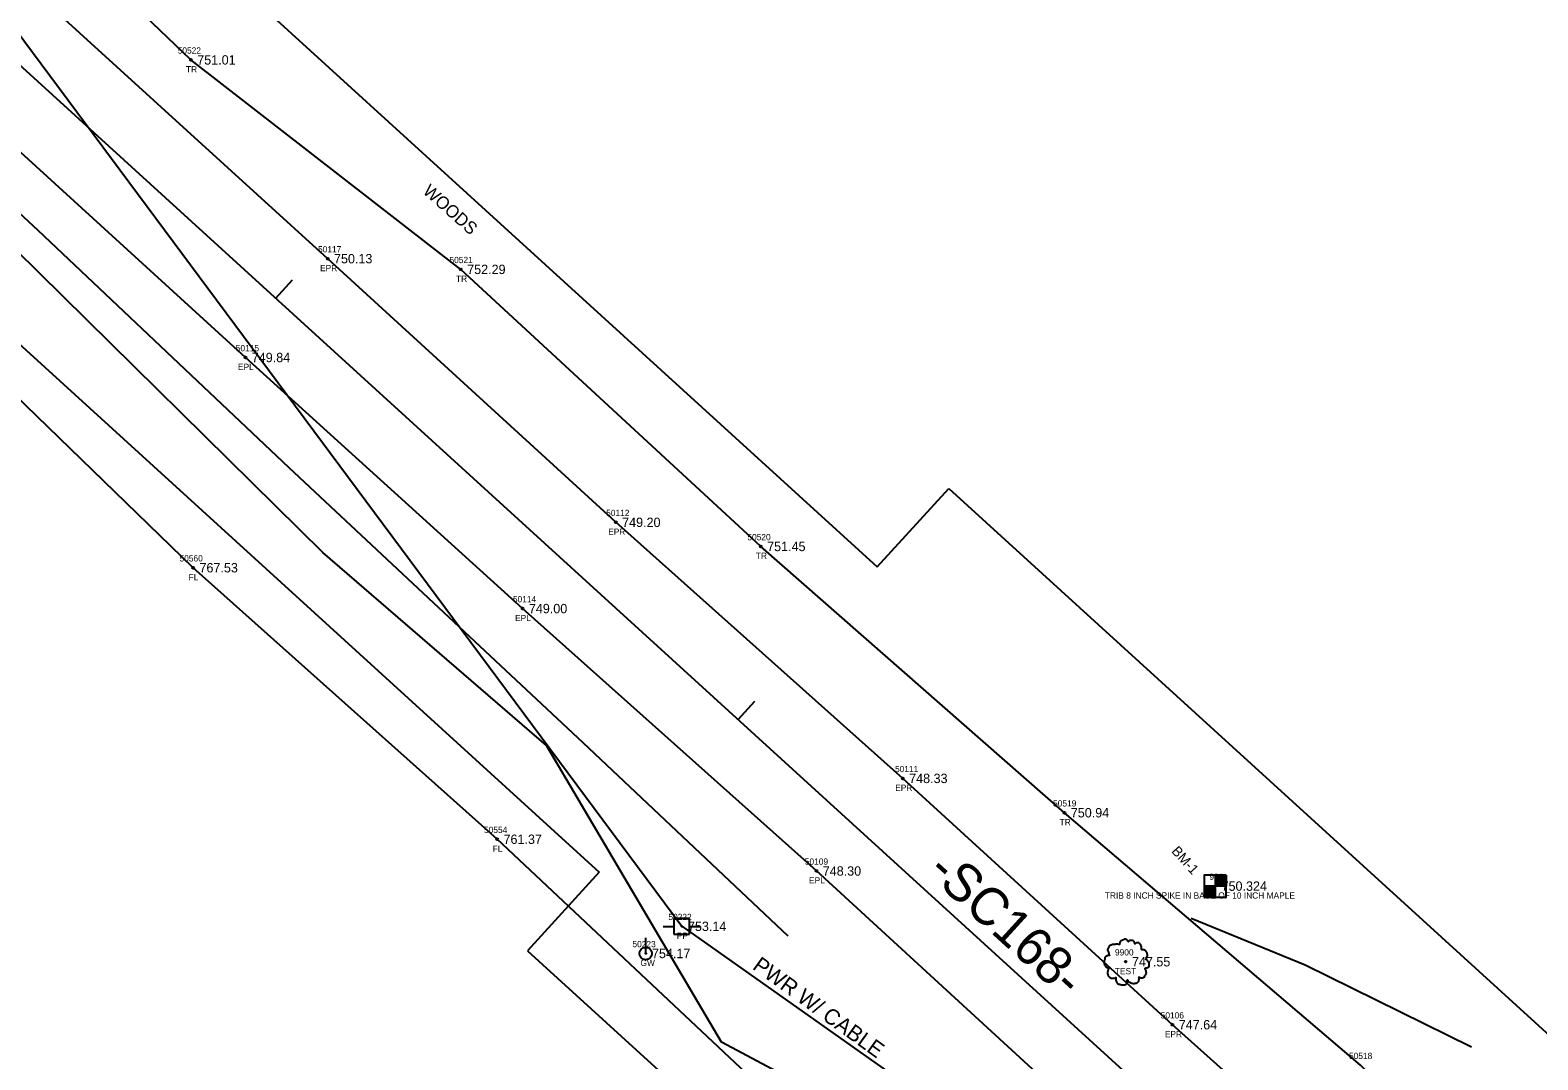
# Model space of a CAD drawing. Extents: x 1378245 to 1381654, y 996521 to 1000567.
# Drawn here: x 1379299.2 to 1379540.2, y 999152.7 to 999317.3 of the extents above; entities that cross this region are included whole.
import ezdxf

# ---------------------------------------------------------------- set-up
doc = ezdxf.new("R2010")
doc.units = 0
for name, color, linetype in [('RD_EX_Fence_Other', 7, 'Continuous'), ('RD_EX_Fence_Other_txCode', 7, 'Continuous'), ('RD_EX_H2O', 7, 'Continuous'), ('RD_EX_Road', 7, 'Continuous'), ('RD_EX_Road_txCode', 7, 'Continuous'), ('RD_EX_RW', 7, 'Continuous'), ('RD_EX_SU_Elec', 7, 'Continuous'), ('RD_EX_TX_Fence_Other_ELEV', 7, 'Continuous'), ('RD_EX_TX_Road_ELEV', 7, 'Continuous'), ('RD_EX_TX_UT_ELEV', 7, 'Continuous'), ('RD_EX_TX_VEG_ELEV', 7, 'Continuous'), ('RD_EX_UT', 7, 'Continuous'), ('RD_EX_UT_txCode', 7, 'Continuous'), ('RD_EX_VEG', 7, 'Continuous'), ('RD_EX_VEG_txCode', 7, 'Continuous'), ('RD_HC_Cl', 7, 'Continuous'), ('RD_HC_Data', 7, 'Continuous'), ('RD_HC_Data_Tic', 7, 'Continuous'), ('RD_HC_Survey', 7, 'Continuous'), ('RD_HC_Survey_ELEV', 7, 'Continuous'), ('RD_HC_Survey_txCode', 7, 'Continuous'), ('RD_SMD_Locator', 7, 'Continuous'), ('RD_TX_Misc1', 7, 'Continuous'), ('RD_TX_Misc2', 7, 'Continuous'), ('RD_TX_Utilities', 7, 'Continuous')]:
    doc.layers.add(name, color=color, linetype=linetype)

msp = doc.modelspace()

# ---------------------------------------------------------------- linework, layer by layer
at = {"layer": 'RD_EX_Fence_Other'}
msp.add_lwpolyline([(1379613.24, 998940.87), (1379574.4, 998986.01), (1379543.59, 999020.83), (1379505.83, 999062.54), (1379472.56, 999095.44), (1379454.3, 999112.36), (1379373.85, 999187.96), (1379325.25, 999231.37), (1379289.51, 999266.01), (1379255.48, 999295.15), (1379213.9, 999334), (1379169.28, 999374.93), (1379148.65, 999391.69), (1379140.06, 999386.4)], dxfattribs=at)
at = {"layer": 'RD_EX_H2O'}
for points in [[(1379420.33, 999172.47), (1379387.59, 999203.38), (1379340.59, 999247.33), (1379300.46, 999285.26), (1379267.64, 999315.76), (1379232.14, 999347.36), (1379190.43, 999387.13)], [(1379484.77, 999175.36), (1379503.01, 999167.88), (1379529.58, 999154.75)]]:
    msp.add_lwpolyline(points, dxfattribs=at)
at = {"layer": 'RD_EX_Road'}
for points in [[(1379637.07, 998987.22), (1379597.14, 999025.68), (1379553.31, 999065.91), (1379510.7, 999104.3), (1379468.49, 999142.89), (1379424.88, 999182.89), (1379377.9, 999224.84), (1379333.61, 999264.98), (1379287.28, 999307.21), (1379240.78, 999348.98)], [(1379652.22, 999003.54), (1379610.67, 999040.91), (1379567.41, 999079.79), (1379524.77, 999119.81), (1379481.79, 999158.31), (1379438.69, 999197.69), (1379392.81, 999238.63), (1379346.75, 999280.78), (1379301.8, 999321.66)]]:
    msp.add_lwpolyline(points, dxfattribs=at)
at = {"layer": 'RD_EX_RW'}
for p, q in [((1378622.31, 999971.52), (1379434.58, 999231.49)), ((1378575.71, 999924.69), (1379390.13, 999182.7)), ((1379434.58, 999231.49), (1379446.02, 999244.05)), ((1379446.02, 999244.05), (1379815.63, 998907.31)), ((1379390.13, 999182.7), (1379378.68, 999170.13)), ((1379378.68, 999170.13), (1379748.28, 998833.39))]:
    msp.add_line(p, q, dxfattribs=at)
at = {"layer": 'RD_EX_SU_Elec'}
msp.add_lwpolyline([(1378514.25, 999944.12), (1378777.7, 999831.22), (1379190.17, 999461.05), (1379403.33, 999174.04), (1379756.94, 998924.25), (1380051.16, 998659.97), (1380327.91, 998390.65), (1380546.23, 998058.37)], dxfattribs=at)
at = {"layer": 'RD_EX_UT'}
for p, q in [((1379400.36, 999174.02), (1379402.09, 999174.02)), ((1379404.57, 999175.3), (1379402.07, 999175.3)), ((1379402.07, 999175.3), (1379402.07, 999172.8)), ((1379404.54, 999174.02), (1379406.36, 999174.02)), ((1379404.57, 999172.8), (1379404.57, 999175.3)), ((1379397.58, 999169.7), (1379397.58, 999172.2)), ((1379402.07, 999172.8), (1379404.57, 999172.8))]:
    msp.add_line(p, q, dxfattribs=at)
msp.add_circle((1379397.58, 999169.7), 1, dxfattribs=at)
at = {"layer": 'RD_EX_VEG'}
for points in [[(1379635.72, 999031.86), (1379598.35, 999066.81), (1379553.67, 999109.8), (1379511.83, 999151.82), (1379464.53, 999192.2), (1379415.99, 999234.77), (1379368.04, 999279.07), (1379324.89, 999312.56), (1379291.58, 999344.45), (1379199.89, 999450.8), (1379227.01, 999457.75)], [(1379621.71, 998986.05), (1379558.91, 999039.89), (1379518.45, 999079.04), (1379470.36, 999123.18), (1379409.67, 999155.52), (1379381.73, 999202.94), (1379345.95, 999233.83), (1379296.88, 999282.18), (1379264.05, 999313.51), (1379229.78, 999344.81), (1379187.41, 999381.54), (1379155.41, 999406.5), (1379144.25, 999379.18), (1379133.7, 999360.09), (1379119.62, 999335.97)]]:
    msp.add_lwpolyline(points, dxfattribs=at)
for centre, radius in [((1379474.3, 999168.38), 0.125), ((1379474.29, 999168.37), 0.00005)]:
    msp.add_circle(centre, radius, dxfattribs=at)
for points in [[(1379474.37, 999171.96), (1379474.22, 999171.98), (1379474.05, 999171.93), (1379473.93, 999171.88), (1379473.82, 999171.84), (1379473.7, 999171.79), (1379473.55, 999171.7), (1379473.44, 999171.6), (1379473.38, 999171.48), (1379473.35, 999171.36), (1379473.33, 999171.23), (1379473.33, 999171.14), (1379473.27, 999171.13), (1379473.19, 999171.14), (1379473.07, 999171.18), (1379472.94, 999171.18), (1379472.82, 999171.18), (1379472.64, 999171.16), (1379472.47, 999171.16), (1379472.33, 999171.14), (1379472.17, 999171.11), (1379471.98, 999171.05), (1379471.81, 999170.99), (1379471.66, 999170.86), (1379471.53, 999170.63), (1379471.47, 999170.45), (1379471.39, 999170.33), (1379471.47, 999170.1), (1379471.56, 999169.93), (1379471.57, 999169.83), (1379471.61, 999169.61), (1379471.66, 999169.5), (1379471.72, 999169.4), (1379471.68, 999169.39), (1379471.49, 999169.36), (1379471.34, 999169.31), (1379471.13, 999169.2), (1379471.02, 999169.09), (1379470.97, 999168.93), (1379470.96, 999168.75), (1379470.91, 999168.65), (1379470.87, 999168.52), (1379470.86, 999168.48), (1379470.83, 999168.32), (1379470.88, 999168.09), (1379470.89, 999167.92), (1379470.96, 999167.8), (1379471.03, 999167.72), (1379471.12, 999167.59), (1379471.32, 999167.48), (1379471.48, 999167.43), (1379471.58, 999167.42), (1379471.49, 999167.17), (1379471.47, 999166.99), (1379471.41, 999166.79), (1379471.41, 999166.75), (1379471.38, 999166.52), (1379471.46, 999166.35), (1379471.49, 999166.17), (1379471.58, 999166.05), (1379471.72, 999165.9), (1379471.88, 999165.79), (1379472.13, 999165.73), (1379472.33, 999165.74), (1379472.62, 999165.83), (1379472.74, 999165.87), (1379472.73, 999165.78), (1379472.74, 999165.59), (1379472.74, 999165.38), (1379472.82, 999165.22), (1379472.87, 999165.08), (1379472.94, 999164.95), (1379473.11, 999164.84), (1379473.3, 999164.8), (1379473.52, 999164.73), (1379473.74, 999164.69), (1379473.99, 999164.68), (1379474.29, 999164.75), (1379474.43, 999164.82), (1379474.48, 999164.9), (1379474.58, 999165.09), (1379474.55, 999165.2), (1379474.57, 999165.5), (1379474.62, 999165.42), (1379474.7, 999165.24), (1379474.95, 999165.09), (1379475.15, 999165), (1379475.39, 999164.93), (1379475.54, 999164.89), (1379475.78, 999164.93), (1379475.97, 999164.97), (1379476.15, 999165.03), (1379476.3, 999165.17), (1379476.39, 999165.3), (1379476.42, 999165.44), (1379476.45, 999165.63), (1379476.48, 999165.72)], [(1379476.48, 999165.72), (1379476.44, 999165.8), (1379476.42, 999165.93), (1379476.45, 999165.92), (1379476.54, 999165.89), (1379476.68, 999165.83), (1379476.79, 999165.79), (1379476.95, 999165.8), (1379477.09, 999165.85), (1379477.32, 999165.99), (1379477.45, 999166.23), (1379477.59, 999166.43), (1379477.63, 999166.59), (1379477.6, 999166.7), (1379477.59, 999166.95), (1379477.49, 999167.08), (1379477.47, 999167.14), (1379477.42, 999167.34), (1379477.45, 999167.37), (1379477.59, 999167.39), (1379477.78, 999167.45), (1379477.92, 999167.52), (1379478.03, 999167.6), (1379478.07, 999167.72), (1379478.05, 999167.92), (1379478.08, 999168.12), (1379478.04, 999168.19), (1379477.99, 999168.27), (1379477.95, 999168.37), (1379477.88, 999168.44), (1379477.83, 999168.52), (1379477.78, 999168.57), (1379477.72, 999168.64), (1379477.63, 999168.7), (1379477.55, 999168.73), (1379477.53, 999168.8), (1379477.6, 999168.9), (1379477.63, 999168.95), (1379477.64, 999169.06), (1379477.75, 999169.24), (1379477.78, 999169.44), (1379477.75, 999169.65), (1379477.73, 999169.79), (1379477.65, 999169.93), (1379477.55, 999170.05), (1379477.49, 999170.14), (1379477.4, 999170.2), (1379477.24, 999170.26), (1379477.12, 999170.29), (1379476.94, 999170.29), (1379476.84, 999170.31), (1379476.85, 999170.34), (1379476.85, 999170.41), (1379476.85, 999170.55), (1379476.82, 999170.78), (1379476.74, 999171.03), (1379476.74, 999171.04), (1379476.69, 999171.16), (1379476.58, 999171.26), (1379476.49, 999171.31), (1379476.39, 999171.38), (1379476.27, 999171.39), (1379476.12, 999171.39), (1379475.98, 999171.36), (1379475.88, 999171.31), (1379475.79, 999171.25), (1379475.75, 999171.33), (1379475.7, 999171.48), (1379475.68, 999171.55), (1379475.6, 999171.64), (1379475.49, 999171.74), (1379475.27, 999171.8), (1379474.95, 999171.76), (1379474.8, 999171.66), (1379474.73, 999171.58), (1379474.7, 999171.64), (1379474.6, 999171.74), (1379474.55, 999171.83), (1379474.47, 999171.89), (1379474.39, 999171.94), (1379474.34, 999171.96)]]:
    msp.add_spline(points, degree=3, dxfattribs=at)
at = {"layer": 'RD_HC_Cl'}
msp.add_line((1378781.54, 999781.8), (1380217.09, 998473.92), dxfattribs=at)
at = {"layer": 'RD_HC_Data_Tic'}
for p, q in [((1379338.43, 999274.44), (1379341.12, 999277.4)), ((1379412.35, 999207.09), (1379415.04, 999210.05))]:
    msp.add_line(p, q, dxfattribs=at)
at = {"layer": 'RD_HC_Survey'}
for p, q in [((1379488.63, 999182.24), (1379488.63, 999178.7)), ((1379488.64, 999182.24), (1379488.64, 999180.47)), ((1379488.67, 999182.24), (1379488.67, 999180.47)), ((1379488.69, 999182.24), (1379488.69, 999180.47)), ((1379488.72, 999182.24), (1379488.72, 999180.47)), ((1379488.74, 999182.24), (1379488.74, 999180.47)), ((1379488.77, 999182.24), (1379488.77, 999180.47)), ((1379488.79, 999182.24), (1379488.79, 999180.47)), ((1379488.82, 999182.24), (1379488.82, 999180.47)), ((1379488.84, 999182.24), (1379488.84, 999180.47)), ((1379488.87, 999182.24), (1379488.87, 999180.47)), ((1379488.89, 999182.24), (1379488.89, 999180.47)), ((1379488.92, 999182.24), (1379488.92, 999180.47)), ((1379488.94, 999182.24), (1379488.94, 999180.47)), ((1379488.97, 999182.24), (1379488.97, 999180.47)), ((1379488.99, 999182.24), (1379488.99, 999180.47)), ((1379489.02, 999182.24), (1379489.02, 999180.47)), ((1379489.04, 999182.24), (1379489.04, 999180.47)), ((1379489.07, 999182.24), (1379489.07, 999180.47)), ((1379489.09, 999182.24), (1379489.09, 999180.47)), ((1379489.12, 999182.24), (1379489.12, 999180.47)), ((1379489.14, 999182.24), (1379489.14, 999180.47)), ((1379489.17, 999182.24), (1379489.17, 999180.47)), ((1379489.19, 999182.24), (1379489.19, 999180.47)), ((1379489.22, 999182.24), (1379489.22, 999180.47)), ((1379489.24, 999182.24), (1379489.24, 999180.47)), ((1379489.27, 999182.24), (1379489.27, 999180.47)), ((1379489.29, 999182.24), (1379489.29, 999180.47)), ((1379489.32, 999182.24), (1379489.32, 999180.47)), ((1379489.34, 999182.24), (1379489.34, 999180.47)), ((1379489.37, 999182.24), (1379489.37, 999180.47)), ((1379489.39, 999182.24), (1379489.39, 999180.47)), ((1379489.42, 999182.24), (1379489.42, 999180.47)), ((1379489.44, 999182.24), (1379489.44, 999180.47)), ((1379489.47, 999182.24), (1379489.47, 999180.47)), ((1379489.49, 999182.24), (1379489.49, 999180.47)), ((1379489.52, 999182.24), (1379489.52, 999180.47)), ((1379489.54, 999182.24), (1379489.54, 999180.47)), ((1379489.57, 999182.24), (1379489.57, 999180.47)), ((1379489.59, 999182.24), (1379489.59, 999180.47)), ((1379489.62, 999182.24), (1379489.62, 999180.47)), ((1379489.64, 999182.24), (1379489.64, 999180.47)), ((1379489.67, 999182.24), (1379489.67, 999180.47)), ((1379489.69, 999182.24), (1379489.69, 999180.47)), ((1379489.72, 999182.24), (1379489.72, 999180.47)), ((1379489.74, 999182.24), (1379489.74, 999180.47)), ((1379489.77, 999182.24), (1379489.77, 999180.47)), ((1379489.79, 999182.24), (1379489.79, 999180.47)), ((1379489.82, 999182.24), (1379489.82, 999180.47)), ((1379489.84, 999182.24), (1379489.84, 999180.47)), ((1379489.87, 999182.24), (1379489.87, 999180.47)), ((1379489.89, 999182.24), (1379489.89, 999180.47)), ((1379489.92, 999182.24), (1379489.92, 999180.47)), ((1379489.94, 999182.24), (1379489.94, 999180.47)), ((1379489.97, 999182.24), (1379489.97, 999180.47)), ((1379489.99, 999182.24), (1379489.99, 999180.47)), ((1379490.02, 999182.24), (1379490.02, 999180.47)), ((1379490.04, 999182.24), (1379490.04, 999180.47)), ((1379490.07, 999182.24), (1379490.07, 999180.47)), ((1379490.09, 999182.24), (1379490.09, 999180.47)), ((1379490.12, 999182.24), (1379490.12, 999180.47)), ((1379490.14, 999182.24), (1379490.14, 999180.47)), ((1379490.17, 999182.24), (1379490.17, 999180.47)), ((1379490.19, 999182.24), (1379490.19, 999180.47)), ((1379490.22, 999182.24), (1379490.22, 999180.47)), ((1379490.24, 999182.24), (1379490.24, 999180.47)), ((1379490.27, 999182.24), (1379490.27, 999180.47)), ((1379490.29, 999182.24), (1379490.29, 999180.47)), ((1379490.32, 999182.24), (1379490.32, 999180.47)), ((1379490.34, 999182.24), (1379490.34, 999180.47)), ((1379490.37, 999182.24), (1379490.37, 999180.47)), ((1379490.39, 999180.47), (1379486.86, 999180.47)), ((1379486.86, 999180.47), (1379486.86, 999178.7)), ((1379486.88, 999180.47), (1379486.88, 999178.7)), ((1379486.91, 999180.47), (1379486.91, 999178.7)), ((1379486.93, 999180.47), (1379486.93, 999178.7)), ((1379486.96, 999180.47), (1379486.96, 999178.7)), ((1379486.98, 999180.47), (1379486.98, 999178.7)), ((1379487.01, 999180.47), (1379487.01, 999178.7)), ((1379487.03, 999180.47), (1379487.03, 999178.7)), ((1379487.06, 999180.47), (1379487.06, 999178.7)), ((1379487.08, 999180.47), (1379487.08, 999178.7)), ((1379487.11, 999180.47), (1379487.11, 999178.7)), ((1379487.13, 999180.47), (1379487.13, 999178.7)), ((1379487.16, 999180.47), (1379487.16, 999178.7)), ((1379487.18, 999180.47), (1379487.18, 999178.7)), ((1379487.21, 999180.47), (1379487.21, 999178.7)), ((1379487.23, 999180.47), (1379487.23, 999178.7)), ((1379487.26, 999180.47), (1379487.26, 999178.7)), ((1379487.28, 999180.47), (1379487.28, 999178.7)), ((1379487.31, 999180.47), (1379487.31, 999178.7)), ((1379487.33, 999180.47), (1379487.33, 999178.7)), ((1379487.36, 999180.47), (1379487.36, 999178.7)), ((1379487.38, 999180.47), (1379487.38, 999178.7)), ((1379487.41, 999180.47), (1379487.41, 999178.7)), ((1379487.43, 999180.47), (1379487.43, 999178.7)), ((1379487.46, 999180.47), (1379487.46, 999178.7)), ((1379487.48, 999180.47), (1379487.48, 999178.7)), ((1379487.51, 999180.47), (1379487.51, 999178.7)), ((1379487.53, 999180.47), (1379487.53, 999178.7)), ((1379487.56, 999180.47), (1379487.56, 999178.7)), ((1379487.58, 999180.47), (1379487.58, 999178.7)), ((1379487.61, 999180.47), (1379487.61, 999178.7)), ((1379487.63, 999180.47), (1379487.63, 999178.7)), ((1379487.66, 999180.47), (1379487.66, 999178.7)), ((1379487.68, 999180.47), (1379487.68, 999178.7)), ((1379487.71, 999180.47), (1379487.71, 999178.7)), ((1379487.73, 999180.47), (1379487.73, 999178.7)), ((1379487.76, 999180.47), (1379487.76, 999178.7)), ((1379487.78, 999180.47), (1379487.78, 999178.7)), ((1379487.81, 999180.47), (1379487.81, 999178.7)), ((1379487.83, 999180.47), (1379487.83, 999178.7)), ((1379487.86, 999180.47), (1379487.86, 999178.7)), ((1379487.88, 999180.47), (1379487.88, 999178.7)), ((1379487.91, 999180.47), (1379487.91, 999178.7)), ((1379487.93, 999180.47), (1379487.93, 999178.7)), ((1379487.96, 999180.47), (1379487.96, 999178.7)), ((1379487.98, 999180.47), (1379487.98, 999178.7)), ((1379488.01, 999180.47), (1379488.01, 999178.7)), ((1379488.03, 999180.47), (1379488.03, 999178.7)), ((1379488.06, 999180.47), (1379488.06, 999178.7)), ((1379488.08, 999180.47), (1379488.08, 999178.7)), ((1379488.11, 999180.47), (1379488.11, 999178.7)), ((1379488.13, 999180.47), (1379488.13, 999178.7)), ((1379488.16, 999180.47), (1379488.16, 999178.7)), ((1379488.18, 999180.47), (1379488.18, 999178.7)), ((1379488.21, 999180.47), (1379488.21, 999178.7)), ((1379488.23, 999180.47), (1379488.23, 999178.7)), ((1379488.26, 999180.47), (1379488.26, 999178.7)), ((1379488.28, 999180.47), (1379488.28, 999178.7)), ((1379488.31, 999180.47), (1379488.31, 999178.7)), ((1379488.33, 999180.47), (1379488.33, 999178.7)), ((1379488.36, 999180.47), (1379488.36, 999178.7)), ((1379488.38, 999180.47), (1379488.38, 999178.7)), ((1379488.41, 999180.47), (1379488.41, 999178.7)), ((1379488.43, 999180.47), (1379488.43, 999178.7)), ((1379488.46, 999180.47), (1379488.46, 999178.7)), ((1379488.48, 999180.47), (1379488.48, 999178.7)), ((1379488.51, 999180.47), (1379488.51, 999178.7)), ((1379488.53, 999180.47), (1379488.53, 999178.7)), ((1379488.56, 999180.47), (1379488.56, 999178.7)), ((1379488.58, 999180.47), (1379488.58, 999178.7)), ((1379488.61, 999180.47), (1379488.61, 999178.7))]:
    msp.add_line(p, q, dxfattribs=at)
msp.add_lwpolyline([(1379490.39, 999182.24), (1379486.86, 999182.24), (1379486.86, 999178.7), (1379490.39, 999178.7)], close=True, dxfattribs=at)
at = {"layer": 'RD_SMD_Locator'}
for centre, radius in [((1379324.89, 999312.56), 0.15), ((1379346.75, 999280.78), 0.15), ((1379368.04, 999279.07), 0.15), ((1379333.61, 999264.98), 0.15), ((1379392.81, 999238.63), 0.15), ((1379415.99, 999234.77), 0.15), ((1379325.25, 999231.37), 0.15), ((1379377.9, 999224.84), 0.15), ((1379438.69, 999197.69), 0.15), ((1379464.53, 999192.2), 0.15), ((1379373.85, 999187.96), 0.15), ((1379424.88, 999182.89), 0.15), ((1379488.63, 999180.47), 0.075), ((1379403.33, 999174.04), 0.075), ((1379397.58, 999169.7), 0.075), ((1379474.3, 999168.38), 0.075), ((1379481.79, 999158.31), 0.15)]:
    msp.add_circle(centre, radius, dxfattribs=at)

# ---------------------------------------------------------------- texts
at = {"layer": 'RD_EX_Fence_Other_txCode'}
for s, p in [('50560', (1379323.06, 999232.37)), ('FL', (1379324.51, 999229.37)), ('50554', (1379371.73, 999188.96)), ('FL', (1379373.12, 999185.96))]:
    msp.add_text(s, height=1, dxfattribs=at).set_placement(p)
at = {"layer": 'RD_EX_Road_txCode'}
for s, p in [('50117', (1379345.2, 999281.78)), ('EPR', (1379345.52, 999278.78)), ('50115', (1379332.05, 999265.98)), ('EPL', (1379332.4, 999262.98)), ('50112', (1379391.26, 999239.63)), ('EPR', (1379391.58, 999236.63)), ('50114', (1379376.35, 999225.84)), ('EPL', (1379376.7, 999222.84)), ('50111', (1379437.43, 999198.69)), ('EPR', (1379437.46, 999195.69)), ('50109', (1379423.01, 999183.89)), ('EPL', (1379423.68, 999180.89)), ('50106', (1379479.9, 999159.31)), ('EPR', (1379480.56, 999156.31))]:
    msp.add_text(s, height=1, dxfattribs=at).set_placement(p)
at = {"layer": 'RD_EX_TX_Fence_Other_ELEV'}
for s, p in [('767.53', (1379326.25, 999230.62)), ('761.37', (1379374.85, 999187.21))]:
    msp.add_text(s, height=1.5, dxfattribs=at).set_placement(p)
at = {"layer": 'RD_EX_TX_Road_ELEV'}
for s, p in [('750.13', (1379347.75, 999280.03)), ('749.84', (1379334.61, 999264.23)), ('749.20', (1379393.81, 999237.88)), ('749.00', (1379378.9, 999224.09)), ('748.33', (1379439.69, 999196.94)), ('748.30', (1379425.88, 999182.14)), ('747.64', (1379482.79, 999157.56))]:
    msp.add_text(s, height=1.5, dxfattribs=at).set_placement(p)
at = {"layer": 'RD_EX_TX_UT_ELEV'}
msp.add_text('754.17', height=1.5, dxfattribs=at).set_placement((1379398.58, 999168.95))
at = {"layer": 'RD_EX_TX_VEG_ELEV'}
for s, p in [('751.01', (1379325.89, 999311.81)), ('752.29', (1379369.04, 999278.32)), ('751.45', (1379416.99, 999234.02)), ('750.94', (1379465.53, 999191.45)), ('747.55', (1379475.3, 999167.63))]:
    msp.add_text(s, height=1.5, dxfattribs=at).set_placement(p)
at = {"layer": 'RD_EX_UT_txCode'}
for s, p in [('50222', (1379401.21, 999175.04)), ('50223', (1379395.46, 999170.7)), ('PP', (1379402.55, 999172.04)), ('GW', (1379396.74, 999167.7))]:
    msp.add_text(s, height=1, dxfattribs=at).set_placement(p)
at = {"layer": 'RD_EX_VEG_txCode'}
for s, p in [('50522', (1379322.77, 999313.56)), ('TR', (1379324.09, 999310.56)), ('50521', (1379366.21, 999280.07)), ('TR', (1379367.25, 999277.07)), ('50520', (1379413.83, 999235.77)), ('TR', (1379415.19, 999232.77)), ('50519', (1379462.7, 999193.2)), ('TR', (1379463.74, 999190.2)), ('9900', (1379472.59, 999169.38)), ('TEST', (1379472.57, 999166.38)), ('50518', (1379510, 999152.82))]:
    msp.add_text(s, height=1, dxfattribs=at).set_placement(p)
at = {"layer": 'RD_HC_Data'}
msp.add_text('-SC168-', height=6, rotation=317.6642, dxfattribs=at).set_placement((1379442.35, 999182.46))
at = {"layer": 'RD_HC_Survey_ELEV'}
for s, p in [('750.324', (1379489.63, 999179.72)), ('753.14', (1379404.33, 999173.29))]:
    msp.add_text(s, height=1.5, dxfattribs=at).set_placement(p)
at = {"layer": 'RD_HC_Survey_txCode'}
for s, p in [('901', (1379487.69, 999181.47)), ('TRIB 8 INCH SPIKE IN BASE OF 10 INCH MAPLE', (1379470.97, 999178.47))]:
    msp.add_text(s, height=1, dxfattribs=at).set_placement(p)
at = {"layer": 'RD_TX_Misc1'}
msp.add_text('BM-1', height=1.6, rotation=311.9056, dxfattribs=at).set_placement((1379481.53, 999185.99))
at = {"layer": 'RD_TX_Misc2'}
msp.add_text('WOODS', height=2, rotation=318.2997, dxfattribs=at).set_placement((1379361.81, 999291.36))
at = {"layer": 'RD_TX_Utilities'}
msp.add_text('PWR W/ CABLE', height=2.5, rotation=324.1676, dxfattribs=at).set_placement((1379414.5, 999167.32))

doc.saveas('drawing.dxf')
